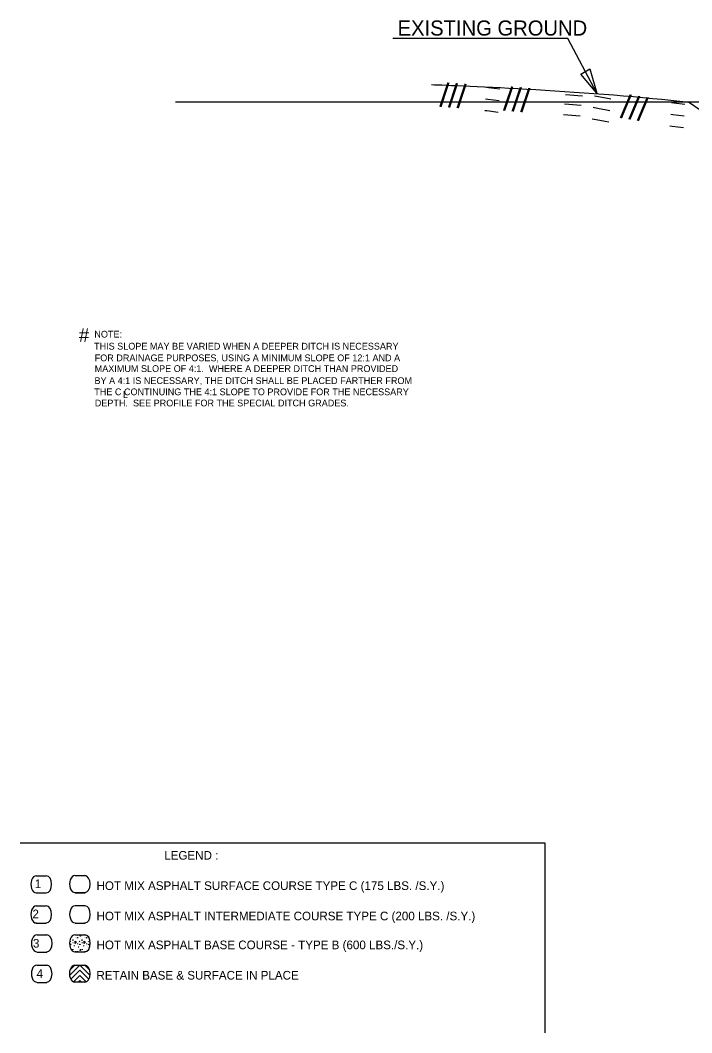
# Model space of a CAD drawing. Extents: x 2061536 to 2063199, y 948597 to 949645.
# Drawn here: x 2061536 to 2062001, y 948597 to 949298 of the extents above; entities that cross this region are included whole.
import ezdxf

# ---------------------------------------------------------------- set-up
doc = ezdxf.new("R2010")
doc.units = 0
for name, color, linetype in [('Default', 7, 'Continuous'), ('RD_TX_TypSect', 7, 'Continuous'), ('RD_XS_Base', 7, 'Continuous'), ('RD_XS_EarthShd', 7, 'Continuous')]:
    doc.layers.add(name, color=color, linetype=linetype)

msp = doc.modelspace()

# ---------------------------------------------------------------- linework, layer by layer
at = {"layer": 'Default'}
for p, q in [((2061914.71, 949284.86), (2061793.77, 949284.86)), ((2061934.76, 949247.21), (2061914.71, 949284.86)), ((2062199.54, 949240.77), (2061643.36, 949240.77)), ((2061535.8, 948728.19), (2061898.91, 948728.19)), ((2061898.91, 948728.19), (2061898.91, 948596.85)), ((2061546.84, 948705.49), (2061553.8, 948705.49)), ((2061573.78, 948705.7), (2061580.74, 948705.7)), ((2061573.78, 948705.7), (2061580.74, 948705.7)), ((2061573.78, 948705.7), (2061573.78, 948705.7)), ((2061546.88, 948693.7), (2061553.85, 948693.7)), ((2061573.78, 948693.7), (2061580.74, 948693.7)), ((2061580.74, 948693.7), (2061573.78, 948693.7)), ((2061546.88, 948684.7), (2061553.85, 948684.7)), ((2061580.74, 948684.7), (2061573.78, 948684.7)), ((2061580.74, 948684.7), (2061580.74, 948684.7)), ((2061546.88, 948672.7), (2061553.85, 948672.7)), ((2061573.78, 948672.7), (2061580.74, 948672.7)), ((2061547.52, 948664.7), (2061554.16, 948664.7)), ((2061570.62, 948659.7), (2061570.62, 948660.2)), ((2061572.2, 948659.2), (2061572.52, 948659.2)), ((2061572.52, 948664.2), (2061572.52, 948664.2)), ((2061573.78, 948664.7), (2061580.74, 948664.7)), ((2061573.78, 948664.7), (2061573.78, 948664.7)), ((2061574.1, 948662.7), (2061574.1, 948662.7)), ((2061575.36, 948664.7), (2061575.36, 948664.7)), ((2061575.36, 948658.7), (2061575.36, 948658.2)), ((2061576.63, 948659.7), (2061576.94, 948660.2)), ((2061578.52, 948659.2), (2061578.84, 948659.2)), ((2061578.84, 948664.2), (2061578.84, 948664.2)), ((2061580.42, 948662.7), (2061580.42, 948662.7)), ((2061581.69, 948658.7), (2061581.69, 948658.2)), ((2061582.96, 948659.7), (2061583.27, 948660.2)), ((2061547.52, 948652.7), (2061554.16, 948652.7)), ((2061572.52, 948654.2), (2061572.52, 948654.7)), ((2061573.46, 948656.7), (2061573.46, 948657.2)), ((2061580.74, 948652.7), (2061573.78, 948652.7)), ((2061574.1, 948653.2), (2061574.1, 948652.7)), ((2061575.36, 948654.7), (2061575.36, 948654.7)), ((2061575.99, 948656.2), (2061576.31, 948656.2)), ((2061576.63, 948656.2), (2061576.63, 948656.2)), ((2061578.84, 948654.2), (2061578.84, 948654.7)), ((2061579.79, 948656.7), (2061579.79, 948657.2)), ((2061580.42, 948653.2), (2061580.42, 948652.7)), ((2061581.69, 948654.7), (2061581.69, 948654.7)), ((2061582.32, 948656.2), (2061582.32, 948656.2)), ((2061582.96, 948656.2), (2061582.96, 948656.2)), ((2061547.45, 948643.69), (2061554.1, 948643.69)), ((2061573.61, 948643.64), (2061580.47, 948643.64)), ((2061547.45, 948631.69), (2061554.1, 948631.69)), ((2061580.47, 948631.82), (2061573.61, 948631.82))]:
    msp.add_line(p, q, dxfattribs=at)
msp.add_lwpolyline([(2061930.02, 949263.95), (2061934.76, 949247.21), (2061923.7, 949260.15)], close=True, dxfattribs=at)
for points in [[(2061858.45, 949251.24), (2061859.93, 949251.03), (2061867.74, 949250.07)], [(2061857.86, 949243.23), (2061859.38, 949243.02), (2061867.22, 949242.05)], [(2061912.4, 949239.71), (2061915.47, 949239.47), (2061920.99, 949239.05), (2061924.1, 949238.81)], [(2061913.18, 949246.12), (2061916.26, 949245.88), (2061921.76, 949245.46), (2061924.87, 949245.22)], [(2061933.23, 949245.35), (2061936.09, 949244.79), (2061942.29, 949243.59), (2061944.67, 949243.18)], [(2061986.58, 949240.61), (2061988.07, 949240.4), (2061995.88, 949239.43)], [(2061857.27, 949235.23), (2061858.82, 949235.01), (2061866.69, 949234.04)], [(2061932.41, 949237.38), (2061935.28, 949236.82), (2061941.52, 949235.62), (2061943.94, 949235.2)], [(2061986, 949232.6), (2061987.52, 949232.39), (2061995.36, 949231.42)], [(2061911.75, 949232.37), (2061914.82, 949232.13), (2061920.33, 949231.7), (2061923.44, 949231.46)], [(2061931.6, 949229.41), (2061934.46, 949228.86), (2061940.74, 949227.64), (2061943.21, 949227.21)], [(2061985.41, 949224.59), (2061986.96, 949224.38), (2061994.83, 949223.41)], [(2061570.62, 948657.7), (2061570.62, 948658.2), (2061570.93, 948658.2), (2061570.62, 948657.7)], [(2061572.2, 948660.7), (2061572.2, 948661.2), (2061572.52, 948661.2), (2061572.2, 948660.7)], [(2061573.78, 948658.7), (2061573.78, 948660.2), (2061574.41, 948659.2), (2061573.78, 948658.7)], [(2061575.36, 948662.2), (2061575.36, 948662.7), (2061575.68, 948662.7), (2061575.36, 948662.2)], [(2061576.94, 948657.7), (2061576.94, 948658.2), (2061577.26, 948658.2), (2061576.94, 948657.7)], [(2061577.26, 948663.7), (2061577.58, 948664.7), (2061577.58, 948663.7), (2061577.26, 948663.7)], [(2061578.52, 948660.7), (2061578.52, 948661.2), (2061578.84, 948661.2), (2061578.52, 948660.7)], [(2061580.11, 948658.7), (2061580.11, 948660.2), (2061580.74, 948659.2), (2061580.11, 948658.7)], [(2061581.69, 948662.2), (2061581.69, 948662.7), (2061582.01, 948662.7), (2061581.69, 948662.2)], [(2061582.96, 948657.7), (2061583.27, 948658.2), (2061583.59, 948658.2), (2061582.96, 948657.7)], [(2061570.93, 948654.7), (2061571.25, 948654.7), (2061571.25, 948654.2)], [(2061575.36, 948652.7), (2061575.36, 948653.2), (2061575.68, 948652.7), (2061575.68, 948652.7)], [(2061577.26, 948653.7), (2061577.58, 948654.7), (2061577.58, 948653.7), (2061577.26, 948653.7)], [(2061581.69, 948653.2), (2061581.69, 948653.2), (2061581.69, 948653.2)], [(2061581.62, 948632.19), (2061581.62, 948632.19), (2061581.62, 948632.19)]]:
    msp.add_lwpolyline(points, dxfattribs=at)
for centre, start_param, end_param in [((2061546.94, 948699.59), 0, 3.141593), ((2061553.8, 948699.59), 3.141593, 6.283185), ((2061573.65, 948699.74), 0, 3.141593), ((2061573.65, 948699.74), 0, 3.141593), ((2061580.51, 948699.74), 3.141593, 6.283185), ((2061580.51, 948699.74), 3.141593, 6.283185), ((2061546.94, 948678.72), 0, 3.141593), ((2061553.8, 948678.72), 3.141593, 6.283185), ((2061573.71, 948678.79), 0, 3.141593), ((2061580.57, 948678.79), 3.141593, 6.283185), ((2061547.3, 948658.73), 0, 3.141593), ((2061554.16, 948658.73), 3.141593, 6.283185), ((2061573.68, 948658.74), 0, 3.141593), ((2061580.54, 948658.74), 3.141593, 6.283185), ((2061547.23, 948637.72), 0, 3.141593), ((2061554.09, 948637.72), 3.141593, 6.283185), ((2061573.61, 948637.73), 0, 3.141593), ((2061580.47, 948637.73), 3.141593, 6.283185)]:
    msp.add_ellipse(centre, major_axis=(0, 5.91), ratio=0.632813, start_param=start_param, end_param=end_param, dxfattribs=at)
msp.add_open_spline([(2061820.46, 949253.05), (2061838.83, 949252.44), (2061935.41, 949248.56), (2061998.37, 949240.77)], degree=3, dxfattribs=at)
at = {"layer": 'RD_XS_Base'}
for p, q in [((2061569.95, 948636.55), (2061577.04, 948643.64)), ((2061570.28, 948640.41), (2061573.51, 948643.64)), ((2061570.79, 948633.85), (2061577.04, 948640.1)), ((2061577.04, 948643.64), (2061584.13, 948636.55)), ((2061577.04, 948640.1), (2061583.29, 948633.85)), ((2061580.58, 948643.63), (2061583.8, 948640.41)), ((2061572.55, 948632.07), (2061577.04, 948636.56)), ((2061575.83, 948631.82), (2061577.04, 948633.03)), ((2061577.04, 948636.56), (2061581.54, 948632.07)), ((2061577.04, 948633.03), (2061578.25, 948631.82))]:
    msp.add_line(p, q, dxfattribs=at)
at = {"layer": 'RD_XS_EarthShd'}
msp.add_line((2062051.29, 949204.39), (2061998.37, 949240.77), dxfattribs=at)

# ---------------------------------------------------------------- texts
at = {"layer": 'Default'}
for s, height, p in [('EXISTING GROUND', 10.45, (2061796.99, 949286.97)), ('NOTE:', 4.687, (2061587.1, 949077.96)), ('THIS SLOPE MAY BE VARIED WHEN A DEEPER DITCH IS NECESSARY', 4.6875, (2061586.89, 949069.65)), ('FOR DRAINAGE PURPOSES, USING A MINIMUM SLOPE OF 12:1 AND A', 4.6875, (2061587.32, 949061.58)), ('MAXIMUM SLOPE OF 4:1.  WHERE A DEEPER DITCH THAN PROVIDED', 4.6875, (2061587.33, 949054.14)), ('BY A 4:1 IS NECESSARY, THE DITCH SHALL BE PLACED FARTHER FROM', 4.6875, (2061587.19, 949045.82)), ('THE C CONTINUING THE 4:1 SLOPE TO PROVIDE FOR THE NECESSARY', 4.6875, (2061587.05, 949038.06)), ('L', 4.69, (2061606.88, 949036.19)), ('DEPTH.  SEE PROFILE FOR THE SPECIAL DITCH GRADES.', 4.6875, (2061587.38, 949030.32)), ('LEGEND :', 6, (2061635.47, 948716.63)), (' 1', 6, (2061543.63, 948696.93)), ('HOT MIX ASPHALT SURFACE COURSE TYPE C (175 LBS. /S.Y.)', 6, (2061588.61, 948695.65)), (' 2', 6, (2061542.03, 948676.09)), ('HOT MIX ASPHALT INTERMEDIATE COURSE TYPE C (200 LBS. /S.Y.)', 6, (2061588.61, 948674.65)), (' 3', 6, (2061542.35, 948655.76)), ('HOT MIX ASPHALT BASE COURSE - TYPE B (600 LBS./S.Y.)', 6, (2061588.61, 948654.65)), ('4', 6, (2061547.07, 948634.75)), ('RETAIN BASE & SURFACE IN PLACE', 6, (2061588.55, 948633.64))]:
    msp.add_text(s, height=height, dxfattribs=at).set_placement(p)
for height, rotation, p in [(16.099, 355.77408, (2061825.76, 949237.93)), (16.096, 355.37803, (2061869.81, 949235.23)), (16.05, 351.20219, (2061950.69, 949230.17))]:
    msp.add_text('///', height=height, rotation=rotation, dxfattribs=at).set_placement(p)
at = {"layer": 'RD_TX_TypSect'}
msp.add_text('#', height=9.5, dxfattribs=at).set_placement((2061576.42, 949074.82))

doc.saveas('drawing.dxf')
